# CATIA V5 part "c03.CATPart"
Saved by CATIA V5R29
Part number: c03
Source: Unknown
Bounding box of the stored display mesh (mm): x -38 to 35, y -200 to 200, z 50.137 to 235.137
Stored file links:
  C:\Users\Administrator\Desktop\프로젝트\Boxfold\TapeCutter\c03.CATPart
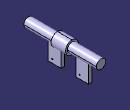
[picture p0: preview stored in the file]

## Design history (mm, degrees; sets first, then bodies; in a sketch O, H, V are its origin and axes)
Body1 (main body)
  Solid1 "PartBody": solid without history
